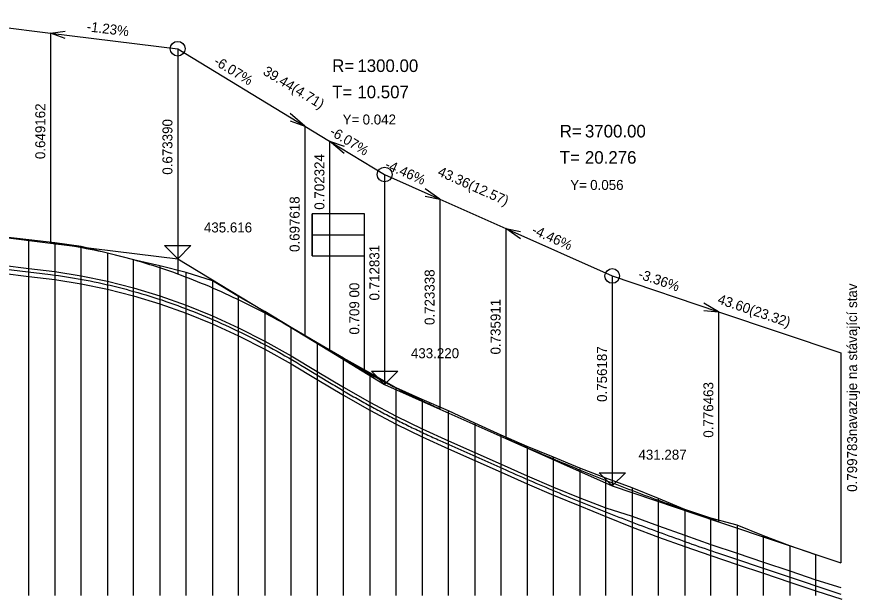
# Model space of a CAD drawing. Extents: x -240 to 1040, y 276 to 593.
# Drawn here: x 647.7 to 808.4, y 403.3 to 514.2 of the extents above; entities that cross this region are included whole.
import ezdxf

# ---------------------------------------------------------------- set-up
doc = ezdxf.new("R2010")
doc.units = 0
doc.layers.add('1', color=7, linetype='Continuous')
doc.layers.add('2', color=7, linetype='Continuous')

# ---------------------------------------------------------------- blocks, each defined once
blk = doc.blocks.new('INTLS')
for p, q in [((0, 30), (-10, 30)), ((-10, 30), (-10, 22)), ((0, 30), (-9.96, 30)), ((0, 30), (0, 30)), ((-10, 26), (0, 26)), ((-9.96, 22), (0, 22))]:
    blk.add_line(p, q)
blk.add_lwpolyline([(-10, 26), (0, 26), (0, 30), (-9.96, 30)], close=True)
at = {"layer": '2'}
for p, q in [((-10, 22), (-10, 30)), ((0, 0), (0, 30))]:
    blk.add_line(p, q, dxfattribs=at)

msp = doc.modelspace()

# ---------------------------------------------------------------- linework, layer by layer
at = {"layer": '1'}
for p, q in [((650, 471.76), (645, 472.31)), ((650, 404), (650, 471.76)), ((655, 471.21), (650, 471.76)), ((655, 471.21), (655, 404)), ((660, 470.49), (655, 471.21)), ((660, 404), (660, 470.49)), ((665, 469.22), (660, 470.49)), ((665, 469.22), (665, 404)), ((670, 467.92), (665, 469.22)), ((670, 404), (670, 467.92)), ((675, 466.78), (670, 467.92)), ((675, 466.78), (675, 404)), ((680, 465.55), (675, 466.78)), ((680, 404), (680, 465.55)), ((685, 463.92), (680, 465.55)), ((685, 463.92), (685, 404)), ((690, 460.97), (685, 463.92)), ((690, 404), (690, 460.97)), ((695, 458.08), (690, 460.97)), ((695, 458.08), (695, 404)), ((700, 455.03), (695, 458.08)), ((700, 404), (700, 455.03)), ((705, 452.1), (700, 455.03)), ((705, 452.1), (705, 404)), ((710, 449.18), (705, 452.1)), ((710, 404), (710, 449.18)), ((715, 446.43), (710, 449.18)), ((715, 446.43), (715, 404)), ((720, 443.55), (715, 446.43)), ((720, 404), (720, 443.55)), ((725, 441.3), (720, 443.55)), ((725, 441.3), (725, 404)), ((730, 439.15), (725, 441.3)), ((730, 404), (730, 439.15)), ((735, 436.79), (730, 439.15)), ((735, 436.79), (735, 404)), ((740, 434.55), (735, 436.79)), ((740, 404), (740, 434.55)), ((745, 432.39), (740, 434.55)), ((745, 432.39), (745, 404)), ((750, 430.33), (745, 432.39)), ((750, 404), (750, 430.33)), ((755, 428.27), (750, 430.33)), ((755, 428.27), (755, 404)), ((760, 426.34), (755, 428.27)), ((760, 404), (760, 426.34)), ((765, 424.47), (760, 426.34)), ((765, 424.47), (765, 404)), ((770, 422.45), (765, 424.47)), ((770, 404), (770, 422.45)), ((775, 420.37), (770, 422.45)), ((775, 420.37), (775, 404)), ((780, 418.7), (775, 420.37)), ((780, 404), (780, 418.7)), ((785, 417.39), (780, 418.7)), ((785, 417.39), (785, 404)), ((790, 415.35), (785, 417.39)), ((790, 404), (790, 415.35)), ((795, 413.46), (790, 415.35)), ((795, 413.46), (795, 404)), ((800, 411.72), (795, 413.46)), ((800, 404), (800, 411.72))]:
    msp.add_line(p, q, dxfattribs=at)
at = {"layer": '2'}
for p, q in [((628.95, 514.24), (654.16, 511.14)), ((654.16, 511.14), (656.96, 511.49)), ((654.16, 511.14), (654.16, 471.14)), ((656.96, 510.09), (654.16, 511.14)), ((654.16, 511.14), (678.39, 508.16)), ((678.39, 508.16), (678.39, 465.22)), ((678.39, 508.16), (702.62, 493.44)), ((702.62, 493.44), (699.82, 495.84)), ((699.82, 494.44), (702.62, 493.44)), ((702.62, 493.44), (702.62, 453.44)), ((702.62, 493.44), (707.32, 490.58)), ((707.32, 490.58), (707.32, 450.58)), ((710.12, 488.18), (707.32, 490.58)), ((707.32, 490.58), (710.12, 489.58)), ((707.32, 490.58), (717.83, 484.2)), ((717.83, 484.2), (717.83, 444.2)), ((717.83, 484.2), (728.34, 479.52)), ((728.34, 479.52), (725.54, 481.46)), ((725.54, 480.06), (728.34, 479.52)), ((728.34, 479.52), (728.34, 439.52)), ((728.34, 479.52), (740.91, 473.91)), ((628.95, 474.24), (654.16, 471.14)), ((740.91, 473.91), (740.91, 433.91)), ((743.71, 471.96), (740.91, 473.91)), ((740.91, 473.91), (743.71, 473.36)), ((740.91, 473.91), (761.19, 464.87)), ((654.92, 471.04), (654.16, 471.14)), ((654.16, 471.14), (678.39, 468.16)), ((655.68, 470.94), (654.92, 471.04)), ((656.43, 470.83), (655.68, 470.94)), ((657.19, 470.72), (656.43, 470.83)), ((657.95, 470.6), (657.19, 470.72)), ((658.7, 470.48), (657.95, 470.6)), ((659.46, 470.35), (658.7, 470.48)), ((660.22, 470.21), (659.46, 470.35)), ((660.98, 470.07), (660.22, 470.21)), ((661.73, 469.92), (660.98, 470.07)), ((662.49, 469.77), (661.73, 469.92)), ((663.25, 469.61), (662.49, 469.77)), ((664, 469.44), (663.25, 469.61)), ((664.76, 469.27), (664, 469.44)), ((665.52, 469.1), (664.76, 469.27)), ((678.39, 468.16), (675.89, 470.66)), ((675.89, 470.66), (680.89, 470.66)), ((680.89, 470.66), (678.39, 468.16)), ((628.95, 468.24), (654.16, 465.14)), ((666.28, 468.92), (665.52, 469.1)), ((667.03, 468.73), (666.28, 468.92)), ((667.79, 468.53), (667.03, 468.73)), ((668.55, 468.34), (667.79, 468.53)), ((669.3, 468.13), (668.55, 468.34)), ((670.06, 467.92), (669.3, 468.13)), ((670.82, 467.7), (670.06, 467.92)), ((671.58, 467.48), (670.82, 467.7)), ((678.39, 468.16), (702.62, 453.44)), ((645, 466.94), (650, 466.32)), ((650, 466.32), (655, 465.71)), ((672.33, 467.25), (671.58, 467.48)), ((673.09, 467.02), (672.33, 467.25)), ((673.85, 466.78), (673.09, 467.02)), ((674.6, 466.54), (673.85, 466.78)), ((675.36, 466.29), (674.6, 466.54)), ((676.12, 466.03), (675.36, 466.29)), ((676.88, 465.77), (676.12, 466.03)), ((645, 465.41), (650, 464.79)), ((650, 464.79), (655, 464.17)), ((654.16, 465.14), (654.92, 465.04)), ((654.92, 465.04), (655.68, 464.94)), ((655, 465.71), (660, 464.92)), ((655.68, 464.94), (656.43, 464.83)), ((656.43, 464.83), (657.19, 464.72)), ((657.19, 464.72), (657.95, 464.6)), ((657.95, 464.6), (658.7, 464.48)), ((658.7, 464.48), (659.46, 464.35)), ((660, 464.92), (665, 463.89)), ((677.63, 465.5), (676.88, 465.77)), ((678.39, 465.23), (677.63, 465.5)), ((679.15, 464.95), (678.39, 465.23)), ((679.9, 464.66), (679.15, 464.95)), ((680.66, 464.37), (679.9, 464.66)), ((681.42, 464.07), (680.66, 464.37)), ((761.19, 464.87), (761.19, 424.87)), ((761.19, 464.87), (781.46, 458.05)), ((655, 464.17), (660, 463.39)), ((659.46, 464.35), (660.22, 464.21)), ((660, 463.39), (665, 462.36)), ((660.22, 464.21), (660.98, 464.07)), ((660.98, 464.07), (661.73, 463.92)), ((661.73, 463.92), (662.49, 463.77)), ((662.49, 463.77), (663.25, 463.61)), ((663.25, 463.61), (664, 463.44)), ((664, 463.44), (664.76, 463.27)), ((664.76, 463.27), (665.52, 463.1)), ((665, 463.89), (670, 462.61)), ((665.52, 463.1), (666.28, 462.92)), ((666.28, 462.92), (667.03, 462.73)), ((682.18, 463.77), (681.42, 464.07)), ((682.93, 463.46), (682.18, 463.77)), ((683.69, 463.15), (682.93, 463.46)), ((684.45, 462.83), (683.69, 463.15)), ((685.2, 462.5), (684.45, 462.83)), ((665, 462.36), (670, 461.08)), ((667.03, 462.73), (667.79, 462.53)), ((667.79, 462.53), (668.55, 462.34)), ((668.55, 462.34), (669.3, 462.13)), ((669.3, 462.13), (670.06, 461.92)), ((670, 462.61), (675, 461.08)), ((670.06, 461.92), (670.82, 461.7)), ((670.82, 461.7), (671.58, 461.48)), ((671.58, 461.48), (672.33, 461.25)), ((672.33, 461.25), (673.09, 461.02)), ((685.96, 462.17), (685.2, 462.5)), ((686.72, 461.84), (685.96, 462.17)), ((687.48, 461.49), (686.72, 461.84)), ((688.23, 461.15), (687.48, 461.49)), ((688.99, 460.79), (688.23, 461.15)), ((670, 461.08), (675, 459.55)), ((673.09, 461.02), (673.85, 460.78)), ((673.85, 460.78), (674.6, 460.54)), ((674.6, 460.54), (675.36, 460.29)), ((675, 461.08), (680, 459.3)), ((675, 459.55), (680, 457.76)), ((675.36, 460.29), (676.12, 460.03)), ((676.12, 460.03), (676.88, 459.77)), ((676.88, 459.77), (677.63, 459.5)), ((689.75, 460.43), (688.99, 460.79)), ((690.5, 460.07), (689.75, 460.43)), ((691.26, 459.7), (690.5, 460.07)), ((692.02, 459.32), (691.26, 459.7)), ((781.46, 458.05), (778.66, 459.69)), ((677.63, 459.5), (678.39, 459.23)), ((678.39, 459.23), (679.15, 458.95)), ((679.15, 458.95), (679.9, 458.66)), ((679.9, 458.66), (680.66, 458.37)), ((680, 459.3), (685, 457.27)), ((680.66, 458.37), (681.42, 458.07)), ((681.42, 458.07), (682.18, 457.77)), ((692.78, 458.94), (692.02, 459.32)), ((693.53, 458.55), (692.78, 458.94)), ((694.29, 458.15), (693.53, 458.55)), ((695.05, 457.75), (694.29, 458.15)), ((778.66, 458.29), (781.46, 458.05)), ((781.46, 458.05), (781.46, 418.05)), ((781.46, 458.05), (804.78, 450.21)), ((680, 457.76), (685, 455.73)), ((682.18, 457.77), (682.93, 457.46)), ((682.93, 457.46), (683.69, 457.15)), ((683.69, 457.15), (684.45, 456.83)), ((684.45, 456.83), (685.2, 456.5)), ((685, 457.27), (690, 454.98)), ((685.2, 456.5), (685.96, 456.17)), ((695.8, 457.35), (695.05, 457.75)), ((696.56, 456.94), (695.8, 457.35)), ((697.32, 456.52), (696.56, 456.94)), ((698.08, 456.1), (697.32, 456.52)), ((685, 455.73), (690, 453.45)), ((685.96, 456.17), (686.72, 455.84)), ((686.72, 455.84), (687.48, 455.49)), ((687.48, 455.49), (688.23, 455.15)), ((688.23, 455.15), (688.99, 454.79)), ((688.99, 454.79), (689.75, 454.43)), ((690, 454.98), (695, 452.45)), ((698.83, 455.67), (698.08, 456.1)), ((699.59, 455.24), (698.83, 455.67)), ((700.35, 454.8), (699.59, 455.24)), ((701.1, 454.35), (700.35, 454.8)), ((689.75, 454.43), (690.5, 454.07)), ((690, 453.45), (695, 450.92)), ((690.5, 454.07), (691.26, 453.7)), ((691.26, 453.7), (692.02, 453.32)), ((692.02, 453.32), (692.78, 452.94)), ((701.86, 453.9), (701.1, 454.35)), ((702.62, 453.44), (701.86, 453.9)), ((702.62, 453.44), (707.32, 450.58)), ((692.78, 452.94), (693.53, 452.55)), ((693.53, 452.55), (694.29, 452.15)), ((694.29, 452.15), (695.05, 451.75)), ((695, 452.45), (700, 449.67)), ((695.05, 451.75), (695.8, 451.35)), ((695, 450.92), (700, 448.14)), ((695.8, 451.35), (696.56, 450.94)), ((696.56, 450.94), (697.32, 450.52)), ((697.32, 450.52), (698.08, 450.1)), ((698.08, 450.1), (698.83, 449.67)), ((707.65, 450.38), (707.32, 450.58)), ((707.32, 450.58), (717.83, 444.2)), ((707.98, 450.19), (707.65, 450.38)), ((708.31, 449.99), (707.98, 450.19)), ((708.64, 449.79), (708.31, 449.99)), ((804.78, 450.21), (804.78, 410.21)), ((698.83, 449.67), (699.59, 449.24)), ((699.59, 449.24), (700.35, 448.8)), ((700, 449.67), (705, 446.67)), ((700.35, 448.8), (701.1, 448.35)), ((701.1, 448.35), (701.86, 447.9)), ((708.97, 449.6), (708.64, 449.79)), ((709.29, 449.4), (708.97, 449.6)), ((709.62, 449.21), (709.29, 449.4)), ((709.95, 449.01), (709.62, 449.21)), ((710.28, 448.82), (709.95, 449.01)), ((710.61, 448.63), (710.28, 448.82)), ((710.94, 448.44), (710.61, 448.63)), ((711.26, 448.25), (710.94, 448.44)), ((700, 448.14), (705, 445.14)), ((701.86, 447.9), (702.62, 447.44)), ((702.62, 447.44), (707.32, 444.58)), ((711.59, 448.06), (711.26, 448.25)), ((711.92, 447.87), (711.59, 448.06)), ((712.25, 447.68), (711.92, 447.87)), ((712.58, 447.5), (712.25, 447.68)), ((712.91, 447.31), (712.58, 447.5)), ((713.23, 447.13), (712.91, 447.31)), ((713.56, 446.94), (713.23, 447.13)), ((713.89, 446.76), (713.56, 446.94)), ((714.22, 446.58), (713.89, 446.76)), ((717.83, 444.2), (715.33, 446.7)), ((715.33, 446.7), (720.33, 446.7)), ((720.33, 446.7), (717.83, 444.2)), ((705, 446.67), (710, 443.66)), ((705, 445.14), (710, 442.13)), ((714.55, 446.4), (714.22, 446.58)), ((714.88, 446.21), (714.55, 446.4)), ((715.2, 446.03), (714.88, 446.21)), ((715.53, 445.86), (715.2, 446.03)), ((715.86, 445.68), (715.53, 445.86)), ((716.19, 445.5), (715.86, 445.68)), ((716.52, 445.32), (716.19, 445.5)), ((716.85, 445.15), (716.52, 445.32)), ((717.17, 444.97), (716.85, 445.15)), ((707.32, 444.58), (707.65, 444.38)), ((707.65, 444.38), (707.98, 444.19)), ((707.98, 444.19), (708.31, 443.99)), ((708.31, 443.99), (708.64, 443.79)), ((708.64, 443.79), (708.97, 443.6)), ((708.97, 443.6), (709.29, 443.4)), ((710, 443.66), (715, 440.82)), ((717.5, 444.8), (717.17, 444.97)), ((717.83, 444.62), (717.5, 444.8)), ((718.16, 444.45), (717.83, 444.62)), ((717.83, 444.2), (728.34, 439.52)), ((718.49, 444.28), (718.16, 444.45)), ((718.82, 444.11), (718.49, 444.28)), ((719.14, 443.94), (718.82, 444.11)), ((719.47, 443.77), (719.14, 443.94)), ((719.8, 443.6), (719.47, 443.77)), ((720.13, 443.43), (719.8, 443.6)), ((709.29, 443.4), (709.62, 443.21)), ((709.62, 443.21), (709.95, 443.01)), ((709.95, 443.01), (710.28, 442.82)), ((710, 442.13), (715, 439.29)), ((710.28, 442.82), (710.61, 442.63)), ((710.61, 442.63), (710.94, 442.44)), ((710.94, 442.44), (711.26, 442.25)), ((711.26, 442.25), (711.59, 442.06)), ((711.59, 442.06), (711.92, 441.87)), ((711.92, 441.87), (712.25, 441.68)), ((720.46, 443.27), (720.13, 443.43)), ((720.79, 443.1), (720.46, 443.27)), ((721.11, 442.94), (720.79, 443.1)), ((721.44, 442.77), (721.11, 442.94)), ((721.77, 442.61), (721.44, 442.77)), ((722.1, 442.45), (721.77, 442.61)), ((722.43, 442.28), (722.1, 442.45)), ((722.76, 442.12), (722.43, 442.28)), ((723.08, 441.96), (722.76, 442.12)), ((723.41, 441.8), (723.08, 441.96)), ((712.25, 441.68), (712.58, 441.5)), ((712.58, 441.5), (712.91, 441.31)), ((712.91, 441.31), (713.23, 441.13)), ((713.23, 441.13), (713.56, 440.94)), ((713.56, 440.94), (713.89, 440.76)), ((713.89, 440.76), (714.22, 440.58)), ((714.22, 440.58), (714.55, 440.4)), ((714.55, 440.4), (714.88, 440.21)), ((715, 440.82), (720, 438.17)), ((723.74, 441.65), (723.41, 441.8)), ((724.07, 441.49), (723.74, 441.65)), ((724.4, 441.33), (724.07, 441.49)), ((724.73, 441.18), (724.4, 441.33)), ((725.05, 441.02), (724.73, 441.18)), ((725.38, 440.87), (725.05, 441.02)), ((725.71, 440.71), (725.38, 440.87)), ((726.04, 440.56), (725.71, 440.71)), ((726.37, 440.41), (726.04, 440.56)), ((726.7, 440.26), (726.37, 440.41)), ((727.02, 440.11), (726.7, 440.26)), ((714.88, 440.21), (715.2, 440.03)), ((715, 439.29), (720, 436.64)), ((715.2, 440.03), (715.53, 439.86)), ((715.53, 439.86), (715.86, 439.68)), ((715.86, 439.68), (716.19, 439.5)), ((716.19, 439.5), (716.52, 439.32)), ((716.52, 439.32), (716.85, 439.15)), ((716.85, 439.15), (717.17, 438.97)), ((717.17, 438.97), (717.5, 438.8)), ((717.5, 438.8), (717.83, 438.62)), ((727.35, 439.96), (727.02, 440.11)), ((727.68, 439.81), (727.35, 439.96)), ((728.01, 439.66), (727.68, 439.81)), ((728.34, 439.52), (728.01, 439.66)), ((728.34, 439.52), (740.91, 433.91)), ((717.83, 438.62), (718.16, 438.45)), ((718.16, 438.45), (718.49, 438.28)), ((718.49, 438.28), (718.82, 438.11)), ((718.82, 438.11), (719.14, 437.94)), ((719.14, 437.94), (719.47, 437.77)), ((719.47, 437.77), (719.8, 437.6)), ((719.8, 437.6), (720.13, 437.43)), ((720, 438.17), (725, 435.72)), ((720.13, 437.43), (720.46, 437.27)), ((720.46, 437.27), (720.79, 437.1)), ((720.79, 437.1), (721.11, 436.94)), ((720, 436.64), (725, 434.19)), ((721.11, 436.94), (721.44, 436.77)), ((721.44, 436.77), (721.77, 436.61)), ((721.77, 436.61), (722.1, 436.45)), ((722.1, 436.45), (722.43, 436.28)), ((722.43, 436.28), (722.76, 436.12)), ((722.76, 436.12), (723.08, 435.96)), ((723.08, 435.96), (723.41, 435.8)), ((723.41, 435.8), (723.74, 435.65)), ((723.74, 435.65), (724.07, 435.49)), ((724.07, 435.49), (724.4, 435.33)), ((725, 435.72), (730, 433.45)), ((724.4, 435.33), (724.73, 435.18)), ((724.73, 435.18), (725.05, 435.02)), ((725, 434.19), (730, 431.92)), ((725.05, 435.02), (725.38, 434.87)), ((725.38, 434.87), (725.71, 434.71)), ((725.71, 434.71), (726.04, 434.56)), ((726.04, 434.56), (726.37, 434.41)), ((726.37, 434.41), (726.7, 434.26)), ((726.7, 434.26), (727.02, 434.11)), ((727.02, 434.11), (727.35, 433.96)), ((727.35, 433.96), (727.68, 433.81)), ((741.54, 433.63), (740.91, 433.91)), ((740.91, 433.91), (761.19, 424.87)), ((727.68, 433.81), (728.01, 433.66)), ((728.01, 433.66), (728.34, 433.52)), ((728.34, 433.52), (740.91, 427.91)), ((730, 433.45), (735, 431.22)), ((742.18, 433.35), (741.54, 433.63)), ((742.81, 433.07), (742.18, 433.35)), ((743.45, 432.79), (742.81, 433.07)), ((744.08, 432.51), (743.45, 432.79)), ((744.71, 432.23), (744.08, 432.51)), ((745.35, 431.96), (744.71, 432.23)), ((730, 431.92), (735, 429.69)), ((735, 431.22), (740, 428.99)), ((745.98, 431.68), (745.35, 431.96)), ((746.61, 431.41), (745.98, 431.68)), ((747.25, 431.14), (746.61, 431.41)), ((747.88, 430.87), (747.25, 431.14)), ((748.51, 430.6), (747.88, 430.87)), ((735, 429.69), (740, 427.46)), ((749.15, 430.33), (748.51, 430.6)), ((749.78, 430.06), (749.15, 430.33)), ((750.42, 429.79), (749.78, 430.06)), ((751.05, 429.53), (750.42, 429.79)), ((751.68, 429.26), (751.05, 429.53)), ((752.32, 429), (751.68, 429.26)), ((740, 428.99), (745, 426.78)), ((740, 427.46), (745, 425.25)), ((740.91, 427.91), (741.54, 427.63)), ((741.54, 427.63), (742.18, 427.35)), ((752.95, 428.74), (752.32, 429)), ((753.58, 428.48), (752.95, 428.74)), ((754.22, 428.22), (753.58, 428.48)), ((754.85, 427.96), (754.22, 428.22)), ((755.48, 427.7), (754.85, 427.96)), ((756.12, 427.44), (755.48, 427.7)), ((756.75, 427.19), (756.12, 427.44)), ((742.18, 427.35), (742.81, 427.07)), ((742.81, 427.07), (743.45, 426.79)), ((743.45, 426.79), (744.08, 426.51)), ((744.08, 426.51), (744.71, 426.23)), ((744.71, 426.23), (745.35, 425.96)), ((745, 426.78), (750, 424.64)), ((745.35, 425.96), (745.98, 425.68)), ((757.39, 426.93), (756.75, 427.19)), ((758.02, 426.68), (757.39, 426.93)), ((758.65, 426.43), (758.02, 426.68)), ((759.29, 426.17), (758.65, 426.43)), ((761.19, 424.87), (758.69, 427.37)), ((758.69, 427.37), (763.69, 427.37)), ((759.92, 425.92), (759.29, 426.17)), ((760.55, 425.67), (759.92, 425.92)), ((763.69, 427.37), (761.19, 424.87)), ((745, 425.25), (750, 423.11)), ((745.98, 425.68), (746.61, 425.41)), ((746.61, 425.41), (747.25, 425.14)), ((747.25, 425.14), (747.88, 424.87)), ((747.88, 424.87), (748.51, 424.6)), ((748.51, 424.6), (749.15, 424.33)), ((749.15, 424.33), (749.78, 424.06)), ((750, 424.64), (755, 422.57)), ((761.19, 425.43), (760.55, 425.67)), ((761.82, 425.18), (761.19, 425.43)), ((761.19, 424.87), (781.46, 418.05)), ((762.45, 424.93), (761.82, 425.18)), ((763.09, 424.69), (762.45, 424.93)), ((763.72, 424.44), (763.09, 424.69)), ((764.36, 424.2), (763.72, 424.44)), ((764.99, 423.96), (764.36, 424.2)), ((749.78, 424.06), (750.42, 423.79)), ((750, 423.11), (755, 421.04)), ((750.42, 423.79), (751.05, 423.53)), ((751.05, 423.53), (751.68, 423.26)), ((751.68, 423.26), (752.32, 423)), ((752.32, 423), (752.95, 422.74)), ((752.95, 422.74), (753.58, 422.48)), ((765.62, 423.72), (764.99, 423.96)), ((766.26, 423.48), (765.62, 423.72)), ((766.89, 423.24), (766.26, 423.48)), ((767.52, 423), (766.89, 423.24)), ((768.16, 422.77), (767.52, 423)), ((768.79, 422.53), (768.16, 422.77)), ((753.58, 422.48), (754.22, 422.22)), ((754.22, 422.22), (754.85, 421.96)), ((754.85, 421.96), (755.48, 421.7)), ((755, 422.57), (760, 420.66)), ((755, 421.04), (760, 419.01)), ((755.48, 421.7), (756.12, 421.44)), ((756.12, 421.44), (756.75, 421.19)), ((756.75, 421.19), (757.39, 420.93)), ((769.42, 422.3), (768.79, 422.53)), ((770.06, 422.06), (769.42, 422.3)), ((770.69, 421.83), (770.06, 422.06)), ((771.33, 421.6), (770.69, 421.83)), ((771.96, 421.37), (771.33, 421.6)), ((772.59, 421.14), (771.96, 421.37)), ((773.23, 420.91), (772.59, 421.14)), ((757.39, 420.93), (758.02, 420.68)), ((758.02, 420.68), (758.65, 420.43)), ((758.65, 420.43), (759.29, 420.17)), ((759.29, 420.17), (759.92, 419.92)), ((759.92, 419.92), (760.55, 419.67)), ((760, 420.66), (765, 419.13)), ((760.55, 419.67), (761.19, 419.43)), ((761.19, 419.43), (761.82, 419.18)), ((773.86, 420.69), (773.23, 420.91)), ((774.49, 420.46), (773.86, 420.69)), ((775.13, 420.24), (774.49, 420.46)), ((775.76, 420.01), (775.13, 420.24)), ((776.39, 419.79), (775.76, 420.01)), ((777.03, 419.57), (776.39, 419.79)), ((777.66, 419.35), (777.03, 419.57)), ((760, 419.01), (765, 416.99)), ((761.82, 419.18), (762.45, 418.93)), ((762.45, 418.93), (763.09, 418.69)), ((763.09, 418.69), (763.72, 418.44)), ((763.72, 418.44), (764.36, 418.2)), ((764.36, 418.2), (764.99, 417.96)), ((764.99, 417.96), (765.62, 417.72)), ((765, 419.13), (770, 417.26)), ((778.29, 419.13), (777.66, 419.35)), ((778.93, 418.91), (778.29, 419.13)), ((779.56, 418.7), (778.93, 418.91)), ((780.2, 418.48), (779.56, 418.7)), ((780.83, 418.27), (780.2, 418.48)), ((781.46, 418.05), (780.83, 418.27)), ((781.46, 418.05), (804.78, 410.21)), ((765, 416.99), (770, 415.12)), ((765.62, 417.72), (766.26, 417.48)), ((766.26, 417.48), (766.89, 417.24)), ((766.89, 417.24), (767.52, 417)), ((767.52, 417), (768.16, 416.77)), ((768.16, 416.77), (768.79, 416.53)), ((768.79, 416.53), (769.42, 416.3)), ((769.42, 416.3), (770.06, 416.06)), ((770, 417.26), (775, 415.46)), ((770, 415.12), (775, 413.32)), ((770.06, 416.06), (770.69, 415.83)), ((770.69, 415.83), (771.33, 415.6)), ((771.33, 415.6), (771.96, 415.37)), ((771.96, 415.37), (772.59, 415.14)), ((772.59, 415.14), (773.23, 414.91)), ((773.23, 414.91), (773.86, 414.69)), ((773.86, 414.69), (774.49, 414.46)), ((775, 415.46), (780, 413.72)), ((774.49, 414.46), (775.13, 414.24)), ((775, 413.32), (780, 411.58)), ((775.13, 414.24), (775.76, 414.01)), ((775.76, 414.01), (776.39, 413.79)), ((776.39, 413.79), (777.03, 413.57)), ((777.03, 413.57), (777.66, 413.35)), ((777.66, 413.35), (778.29, 413.13)), ((778.29, 413.13), (778.93, 412.91)), ((780, 413.72), (785, 412.04)), ((778.93, 412.91), (779.56, 412.7)), ((779.56, 412.7), (780.2, 412.48)), ((780, 411.58), (785, 409.9)), ((780.2, 412.48), (780.83, 412.27)), ((780.83, 412.27), (781.46, 412.05)), ((781.46, 412.05), (804.78, 404.21)), ((785, 412.04), (790, 410.36)), ((785, 409.9), (790, 408.22)), ((790, 410.36), (795, 408.67)), ((790, 408.22), (795, 406.54)), ((795, 408.67), (800, 406.99)), ((795, 406.54), (800, 404.86))]:
    msp.add_line(p, q, dxfattribs=at)
for points in [[(645, 466.94), (650, 466.32), (655, 465.71), (660, 464.92), (665, 463.89), (670, 462.61), (675, 461.08), (680, 459.3), (685, 457.27), (690, 454.98), (695, 452.45), (700, 449.67), (705, 446.67), (710, 443.66), (715, 440.82), (720, 438.17), (725, 435.72), (730, 433.45), (735, 431.22), (740, 428.99), (745, 426.78), (750, 424.64), (755, 422.57), (760, 420.66), (765, 419.13), (770, 417.26), (775, 415.46), (780, 413.72), (785, 412.04), (790, 410.36), (795, 408.67), (800, 406.99), (804.75, 405.54)], [(645, 465.41), (650, 464.79), (655, 464.17), (660, 463.39), (665, 462.36), (670, 461.08), (675, 459.55), (680, 457.76), (685, 455.73), (690, 453.45), (695, 450.92), (700, 448.14), (705, 445.14), (710, 442.13), (715, 439.29), (720, 436.64), (725, 434.19), (730, 431.92), (735, 429.69), (740, 427.46), (745, 425.25), (750, 423.11), (755, 421.04), (760, 419.01), (765, 416.99), (770, 415.12), (775, 413.32), (780, 411.58), (785, 409.9), (790, 408.22), (795, 406.54), (800, 404.86), (804.92, 403.29)]]:
    msp.add_lwpolyline(points, dxfattribs=at)
for centre in [(678.39, 508.16), (717.83, 484.2), (761.19, 464.87)]:
    msp.add_circle(centre, 1.4, dxfattribs=at)

# ---------------------------------------------------------------- block references
msp.add_blockref('INTLS', (714, 446.7))

# ---------------------------------------------------------------- texts
msp.add_text('0.709 00', height=1.9, rotation=90).set_placement((713, 453.7))
for s, rotation, p in [(' -1.23%', 352.9923, (660.28, 511.59)), (' -6.07%', 328.7218, (684.5, 505.65)), ('39.44(4.71)', 328.7218, (694.49, 503.36)), ('0.649162', 90, (653.16, 487.14)), ('0.673390', 90, (677.39, 484.16)), (' -6.07%', 328.7218, (706.58, 492.24)), ('0.702324', 90, (706.35, 477.49)), (' -4.46%', 335.9704, (717.08, 485.73)), ('43.36(12.57)', 335.9704, (727.78, 484.08)), ('0.697618', 90, (701.62, 469.44)), (' -4.46%', 335.9704, (745.05, 473.26)), ('0.712831', 90, (716.83, 460.2)), ('0.723338', 90, (727.34, 455.52)), (' -3.36%', 341.4149, (765.33, 464.68)), ('0.799783navazuje na stávající stav', 90, (807.85, 423.74)), ('43.60(23.32)', 341.4149, (781.12, 459.67)), ('0.735911', 90, (739.91, 449.91)), ('0.756187', 90, (760.19, 440.87)), ('0.776463', 90, (780.46, 434.05))]:
    msp.add_text(s, height=1.9, rotation=rotation, dxfattribs=at).set_placement(p)
for s, height, p in [('1300.00', 2.4, (712.63, 503.73)), ('R=', 2.4, (707.83, 503.73)), ('T=', 2.4, (707.83, 498.73)), ('10.507', 2.4, (712.63, 498.73)), ('Y=', 1.9, (709.83, 493.73)), ('0.042', 1.9, (713.63, 493.73)), ('R=', 2.4, (751.19, 491.26)), ('3700.00', 2.4, (755.99, 491.26)), ('T=', 2.4, (751.19, 486.26)), ('20.276', 2.4, (755.99, 486.26)), ('Y=', 1.9, (753.19, 481.26)), ('0.056', 1.9, (756.99, 481.26)), ('435.616', 1.9, (683.39, 473.16)), ('433.220', 1.9, (722.83, 449.2)), ('431.287', 1.9, (766.19, 429.87))]:
    msp.add_text(s, height=height, dxfattribs=at).set_placement(p)

doc.saveas('drawing.dxf')
